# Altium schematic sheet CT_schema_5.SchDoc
size 511 x 385 mm
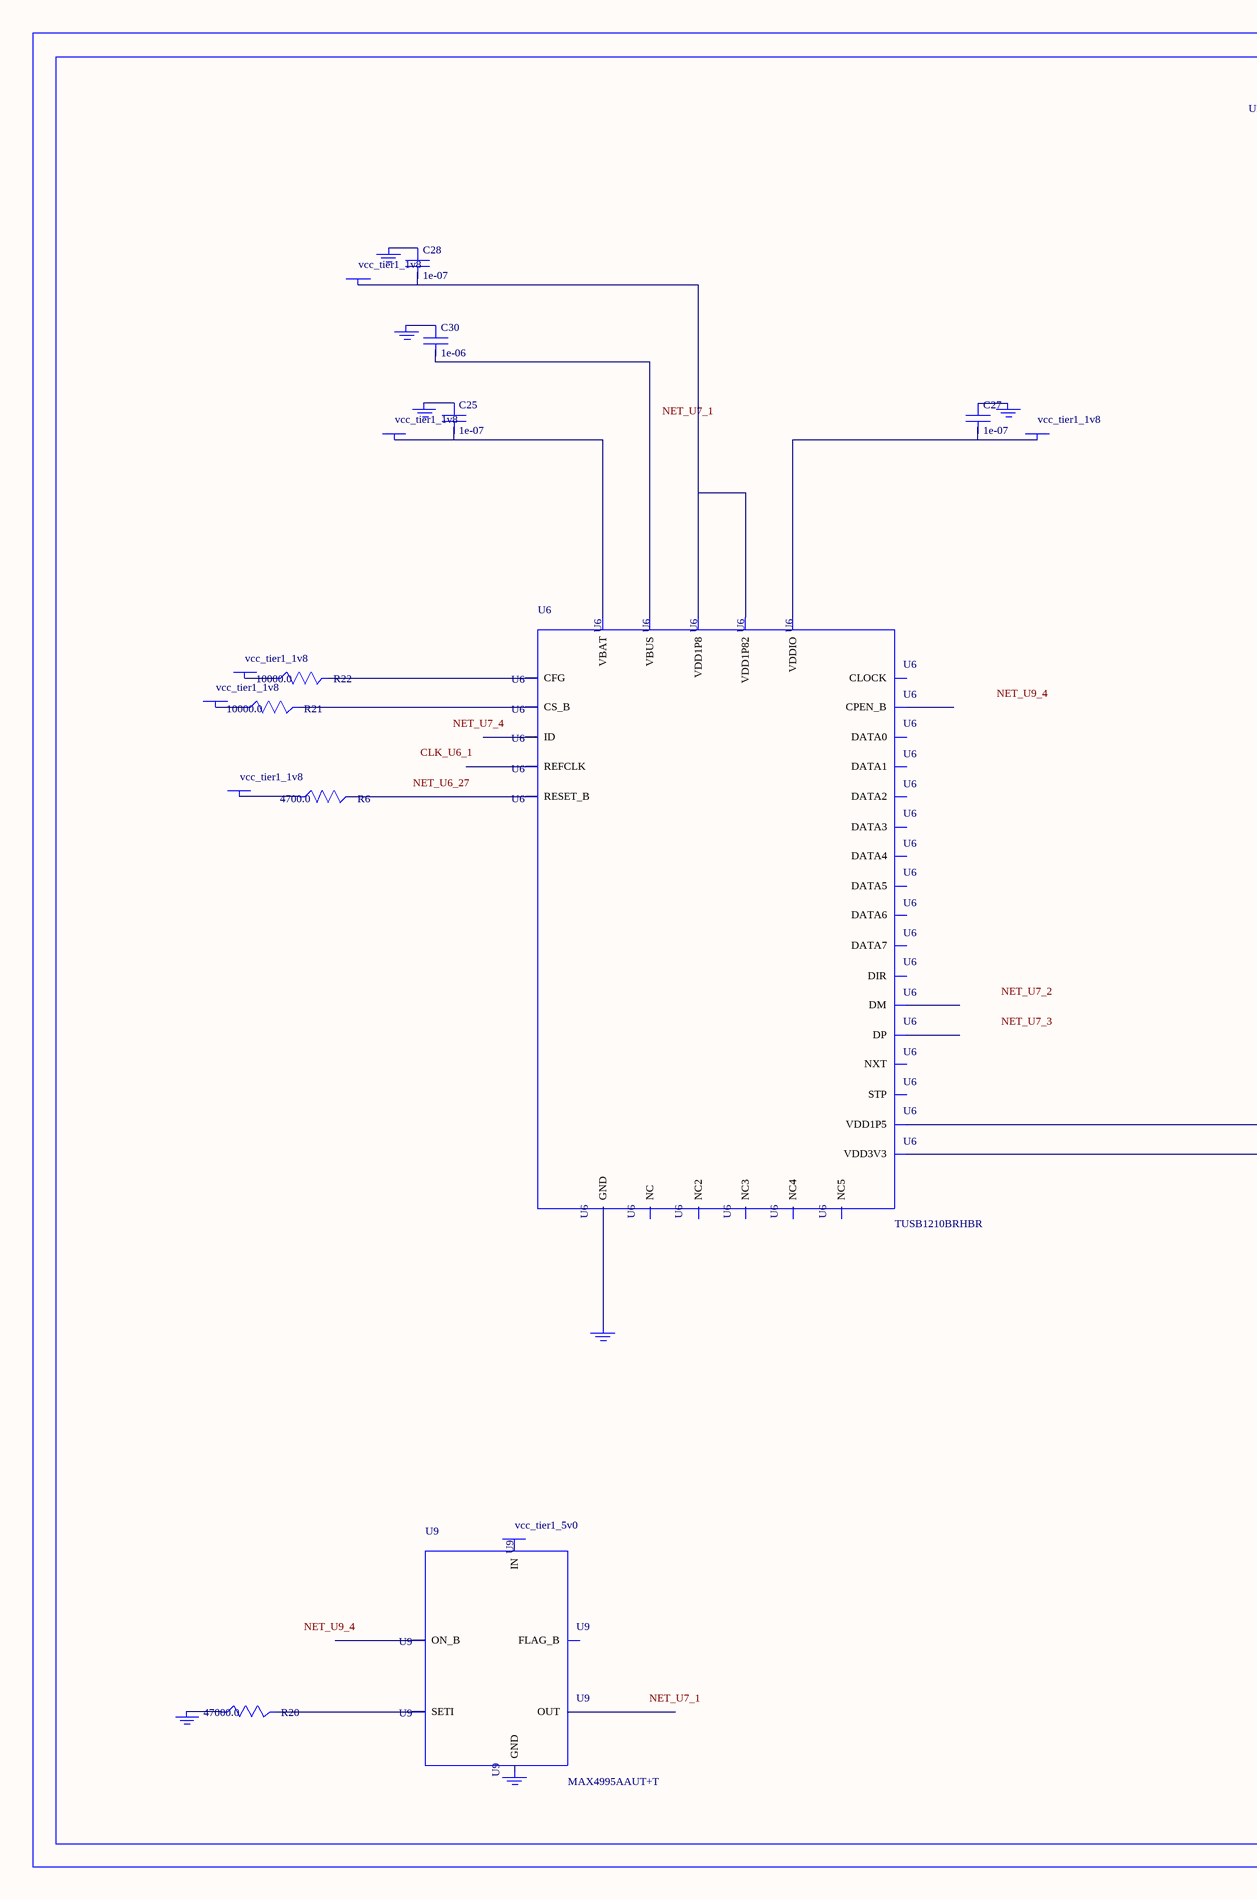
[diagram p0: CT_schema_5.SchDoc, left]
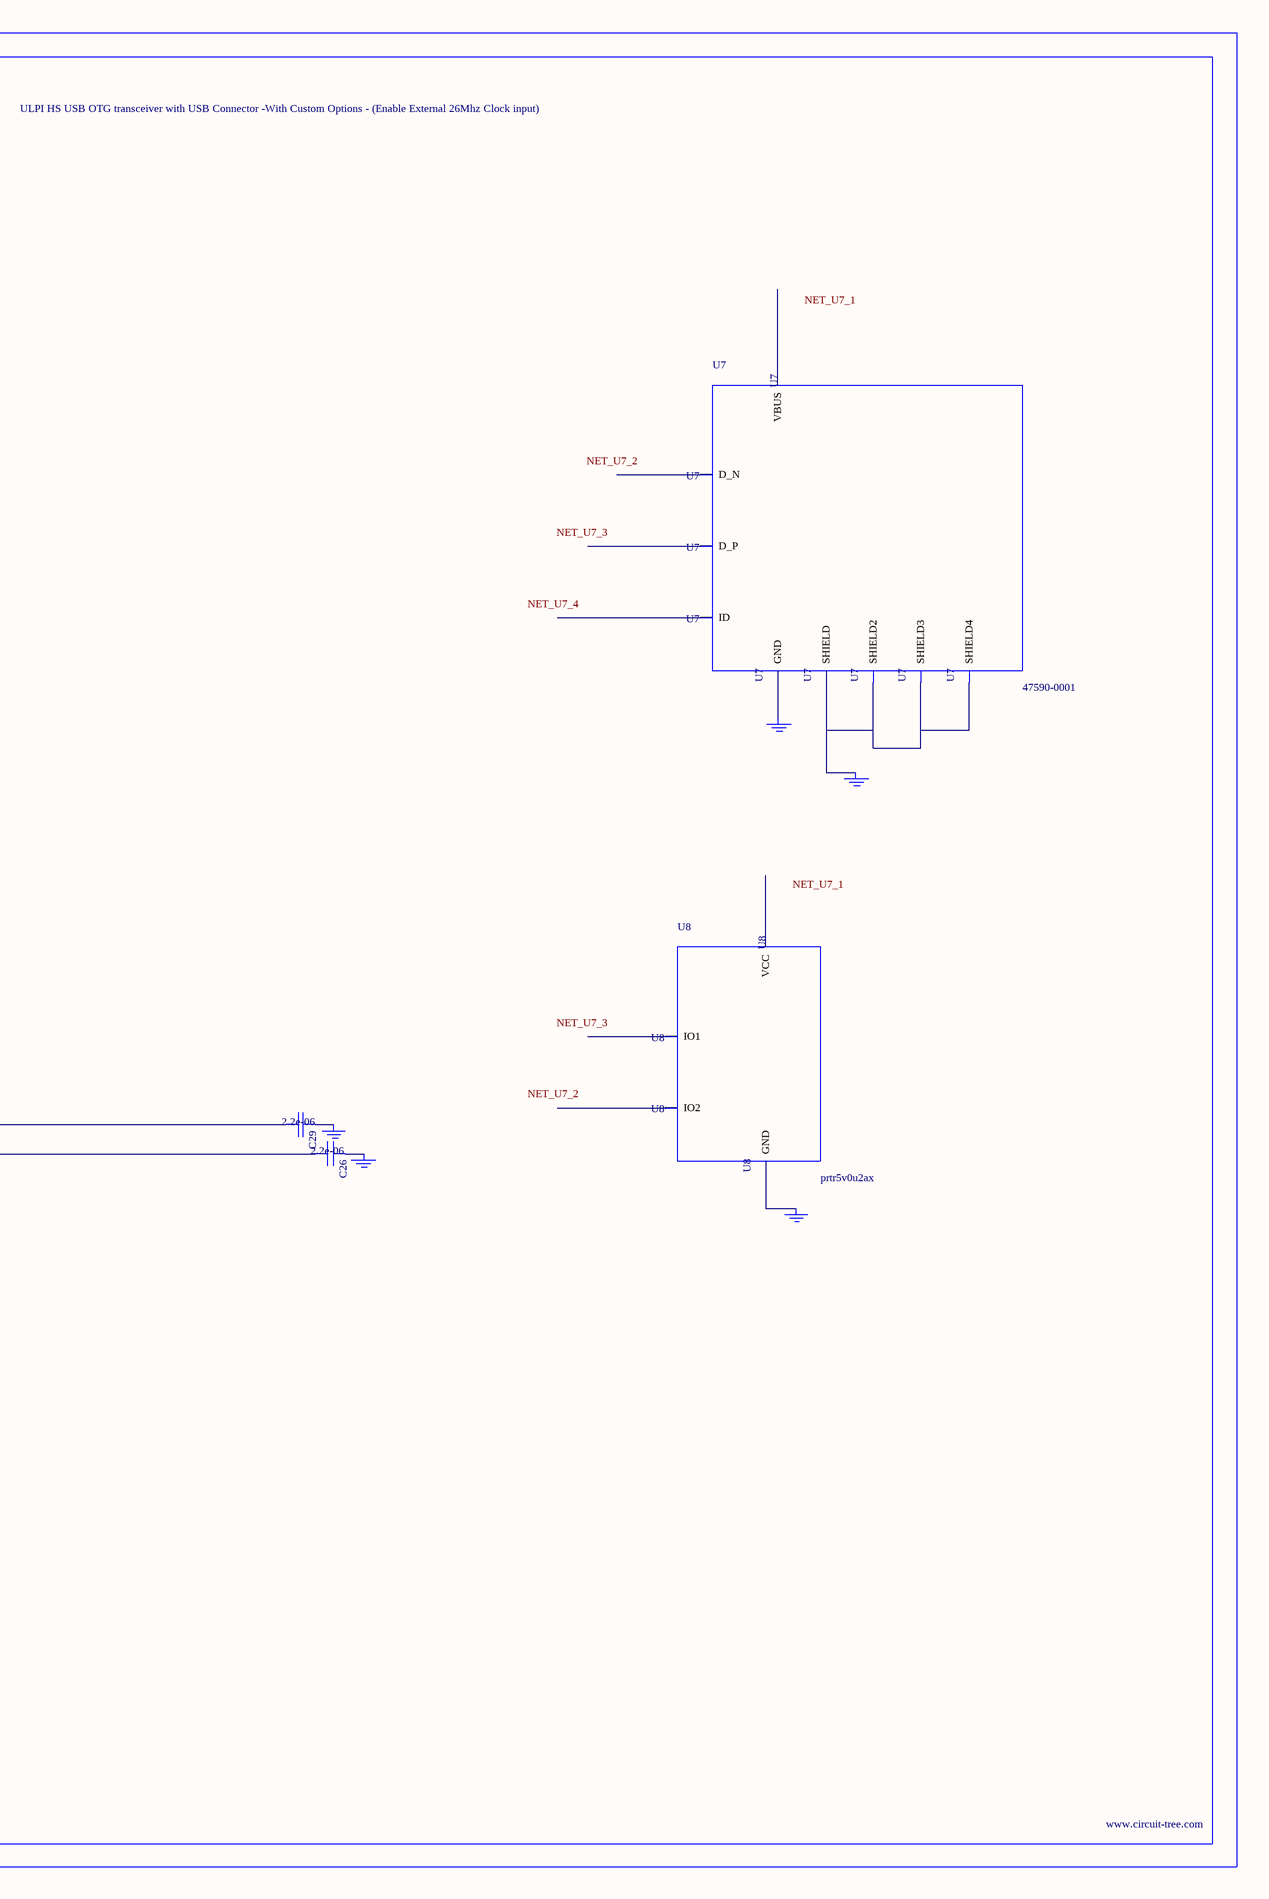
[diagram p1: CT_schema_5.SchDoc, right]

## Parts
BORDER4  (no value)
C25  1e-07  [C0402]
C26  2.2e-06  [C0603]
C27  1e-07  [C0402]
C28  1e-07  [C0402]
C29  2.2e-06  [C0603]
C30  1e-06  [C0603]
GND_INSTANCE_4_0  (no value)
GND_INSTANCE_4_1  (no value)
GND_INSTANCE_4_2  (no value)
GND_INSTANCE_4_3  (no value)
GND_INSTANCE_4_4  (no value)
GND_INSTANCE_4_5  (no value)
GND_INSTANCE_4_6  (no value)
GND_INSTANCE_4_7  (no value)
GND_INSTANCE_4_8  (no value)
GND_INSTANCE_4_9  (no value)
GND_INSTANCE_4_10  (no value)
GND_INSTANCE_4_11  (no value)
POWER_INSTANCE_4_0  vcc_tier1_1v8
POWER_INSTANCE_4_1  vcc_tier1_1v8
POWER_INSTANCE_4_2  vcc_tier1_1v8
POWER_INSTANCE_4_3  vcc_tier1_1v8
POWER_INSTANCE_4_4  vcc_tier1_1v8
POWER_INSTANCE_4_5  vcc_tier1_1v8
POWER_INSTANCE_4_6  vcc_tier1_5v0
R6  4700.0  [R0603]
R20  47000.0  [R0603]
R21  10000.0  [R0603]
R22  10000.0  [R0603]
U6  TUSB1210BRHBR  [RHB32_3P45X3P45]
U7  47590-0001  [MICRO_USB_AB]
U8  prtr5v0u2ax  [SOT143B]
U9  MAX4995AAUT+T  [SOT-23-6]

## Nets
NetC25_1: C25.1 GND_INSTANCE_4_2.0(GND)
NetC25_2: C25.2 POWER_INSTANCE_4_2.0(PWR) U6.21(VBAT)
NetC26_1: C26.1 GND_INSTANCE_4_1.0(GND)
NetC26_2: C26.2 U6.20(VDD3V3)
NetC27_1: C27.1 GND_INSTANCE_4_5.0(GND)
NetC27_2: C27.2 POWER_INSTANCE_4_4.0(PWR) U6.32(VDDIO)
NetC28_1: C28.1 GND_INSTANCE_4_4.0(GND)
NetC28_2: C28.2 POWER_INSTANCE_4_3.0(PWR) U6.28(VDD1P8) U6.30(VDD1P82)
NetC29_1: C29.1 GND_INSTANCE_4_0.0(GND)
NetC29_2: C29.2 U6.12(VDD1P5)
NetC30_1: C30.1 GND_INSTANCE_4_3.0(GND)
NetC30_2: C30.2 U6.22(VBUS)
NetGND_INSTANCE_4_6_0: GND_INSTANCE_4_6.0(GND) U6.33(GND)
NetGND_INSTANCE_4_7_0: GND_INSTANCE_4_7.0(GND) U7.6(SHIELD) U7.7(SHIELD2) U7.8(SHIELD3) U7.9(SHIELD4)
NetGND_INSTANCE_4_8_0: GND_INSTANCE_4_8.0(GND) U7.5(GND)
NetGND_INSTANCE_4_9_0: GND_INSTANCE_4_9.0(GND) U8.1(GND)
NetGND_INSTANCE_4_10_0: GND_INSTANCE_4_10.0(GND) R20.1
NetPOWER_INSTANCE_4_0_0: POWER_INSTANCE_4_0.0(PWR) R21.1
NetPOWER_INSTANCE_4_1_0: POWER_INSTANCE_4_1.0(PWR) R22.1
NetPOWER_INSTANCE_4_5_0: POWER_INSTANCE_4_5.0(PWR) R6.1
NetR6_2: R6.2 U6.27(RESET_B)
NetR20_2: R20.2 U9.3(SETI)
NetR21_2: R21.2 U6.11(CS_B)
NetR22_2: R22.2 U6.14(CFG)

Not connected (* = marked no-connect by the designer): GND_INSTANCE_4_11 0(GND); POWER_INSTANCE_4_6 0(PWR); U6 1(REFCLK) 2(NXT) 3(DATA0) 4(DATA1) 5(DATA2) 6(DATA3) 7(DATA4) 8(NC) 9(DATA5) 10(DATA6) 13(DATA7) 15(NC2) 16(NC3) 17(CPEN_B) 18(DP) 19(DM) 23(ID) 24(NC4) 25(NC5) 26(CLOCK) 29(STP) 31(DIR); U7 1(VBUS) 2(D_N) 3(D_P) 4(ID); U8 2(IO1) 3(IO2) 4(VCC); U9 1(OUT) 2(GND) 4(ON_B) 5(IN) 6(FLAG_B)

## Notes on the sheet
- Labels drawn without touching a wire or pin: CLK_U6_1, NET_U6_27, NET_U7_1, NET_U7_2, NET_U7_3, NET_U7_4, NET_U9_4

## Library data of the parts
BORDER4 = BORDER_PAGE4
C25 C27 C28 = C0402C104K3RACTU
C26 C29 = C0603C225K8RACTU
C30 = C0603C105K3RACTU
GND_INSTANCE_4_0-GND_INSTANCE_4_11 = GND
POWER_INSTANCE_4_0-POWER_INSTANCE_4_6 = PWR
R6 = RC0603JR-074K7L
R20 = RC0603JR-0747KL
R21 R22 = RC0603JR-0710KL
